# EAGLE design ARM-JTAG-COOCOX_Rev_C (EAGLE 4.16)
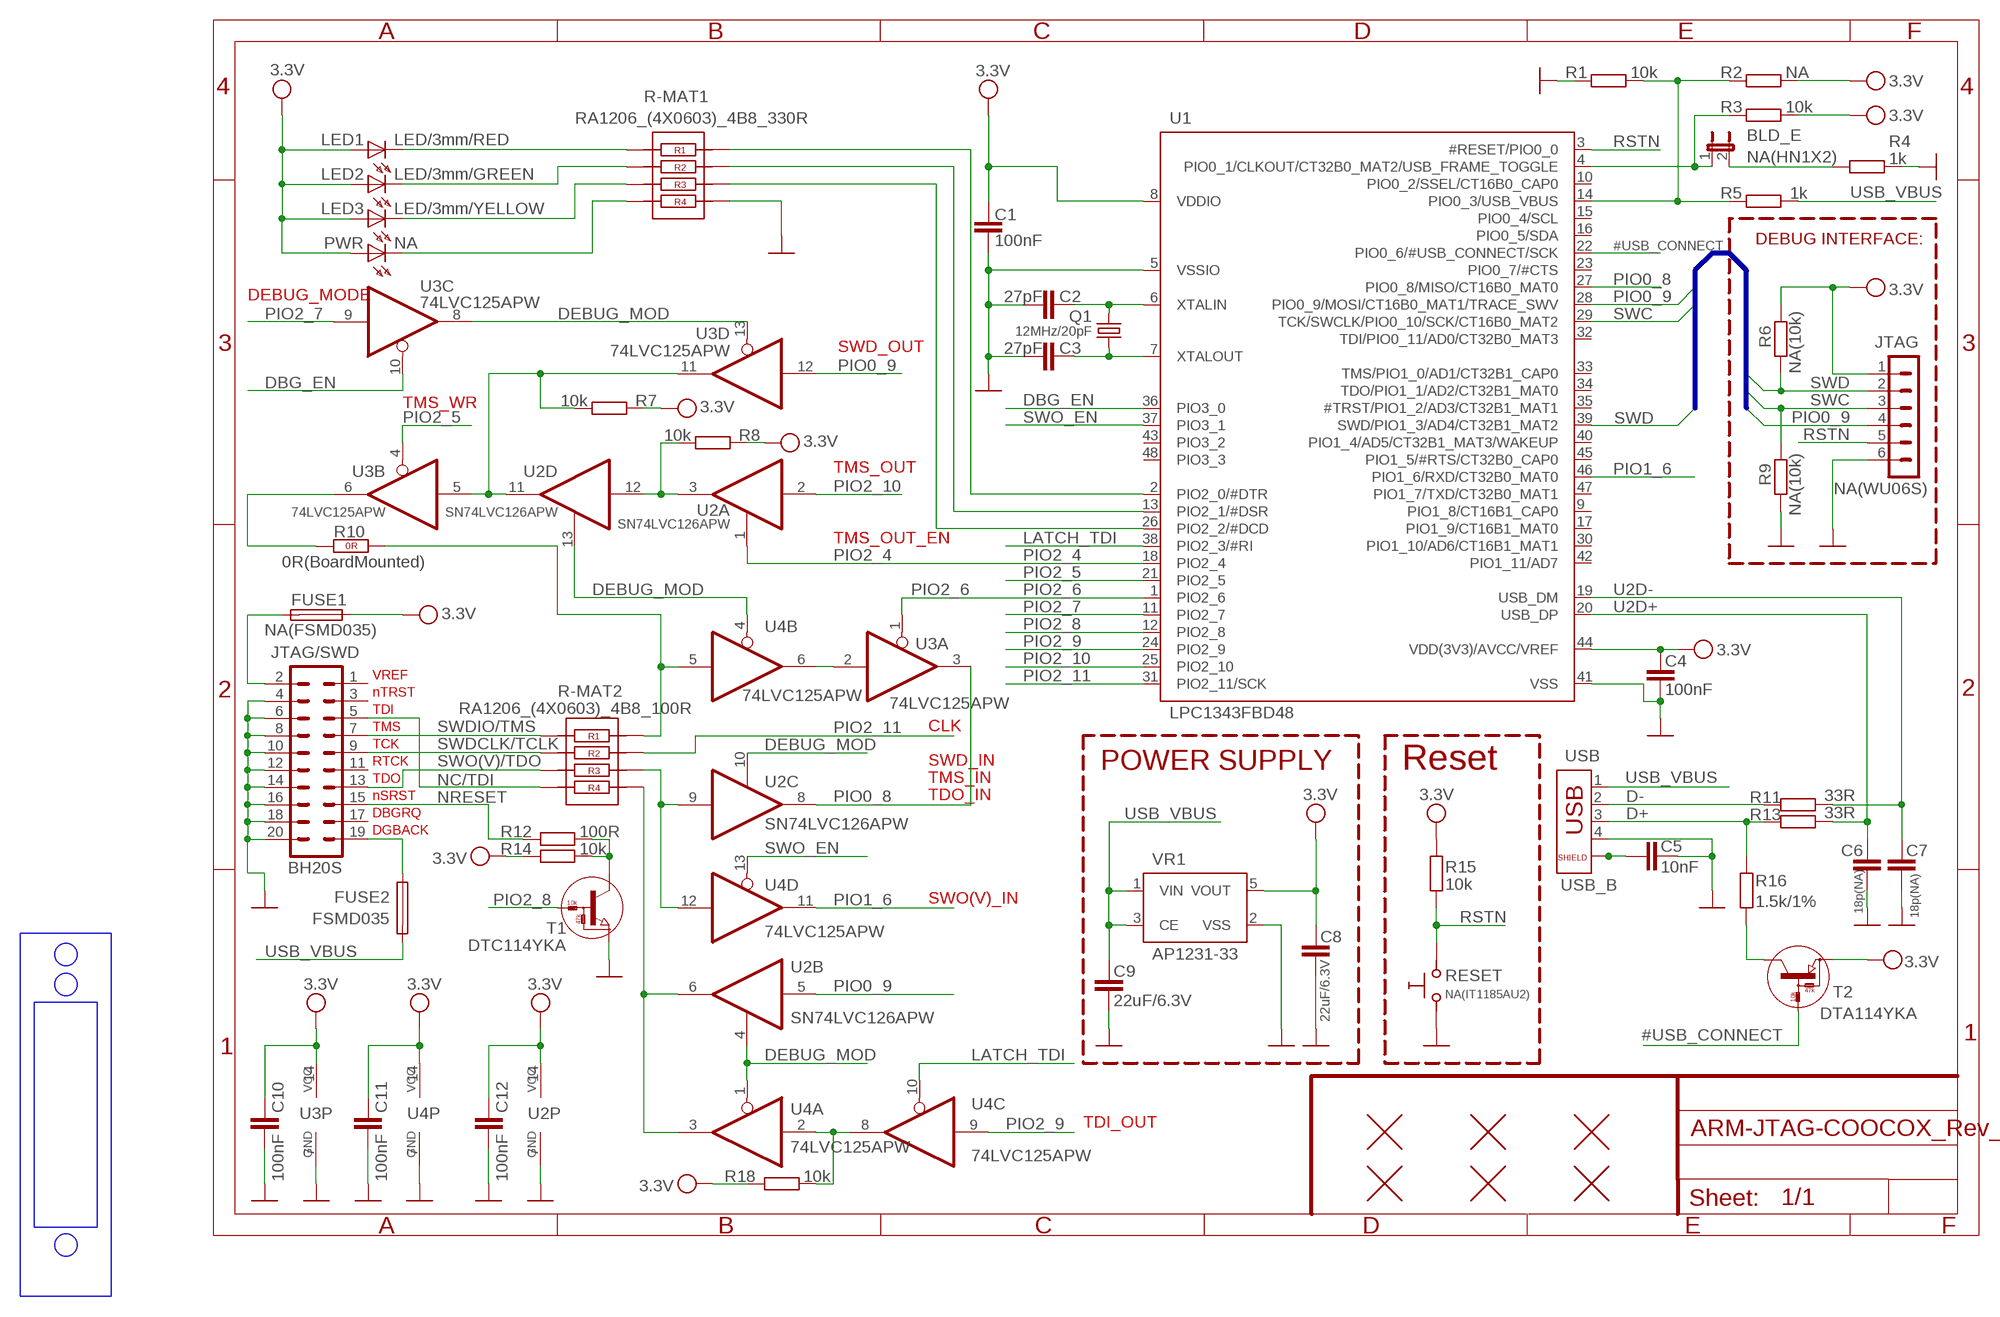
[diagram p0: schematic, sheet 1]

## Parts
BLD_E  NA(HN1X2)  JP1E  [JP1]
C1  100nF  C-EUC0603_DWS  [C0603_DWS]
C2  27pF  C-EUC0603_DWS  [C0603_DWS]
C3  27pF  C-EUC0603_DWS  [C0603_DWS]
C4  100nF  C-EUC0603_DWS  [C0603_DWS]
C5  10nF  C-EUC0603_DWS  [C0603_DWS]
C6  18p(NA)  C-EUC0603_DWS_NA  [C0603_DWS_NA]
C7  18p(NA)  C-EUC0603_DWS_NA  [C0603_DWS_NA]
C8  22uF/6.3V  C-EUC0603_DWS  [C0603_DWS]
C9  22uF/6.3V  C-EUC0603_DWS  [C0603_DWS]
C10  100nF  C-EUC0603_DWS  [C0603_DWS]
C11  100nF  C-EUC0603_DWS  [C0603_DWS]
C12  100nF  C-EUC0603_DWS  [C0603_DWS]
FUSE1  NA(FSMD035)  FUSE  [1206]
FUSE2  FSMD035  FUSE  [1206]
JTAG  NA(WU06S)  CON6WUO6S  [WU06S]
JTAG/SWD  BH20S  ML20CHANGED  [ML20L_PADS_CHANGED]
LED1  LED/3mm/RED  LEDLED_SMD_90  [LED_PADS]
LED2  LED/3mm/GREEN  LEDLED_SMD_90  [LED_PADS]
LED3  LED/3mm/YELLOW  LEDLED_SMD_90  [LED_PADS]
PWR  NA  LEDLED_SMD_90  [LED_PADS]
Q1  12MHz/20pF  HC49/S1  [HC49/SMD2_THIN]
R1  10k  R-EU_R0603_5MIL_DWS  [R0603_5MIL_DWS]
R2  NA  R-EU_R0603_5MIL_DWS  [R0603_5MIL_DWS]
R3  10k  R-EU_R0603_5MIL_DWS  [R0603_5MIL_DWS]
R4  1k  R-EU_R0603_5MIL_DWS  [R0603_5MIL_DWS]
R5  1k  R-EU_R0603_5MIL_DWS  [R0603_5MIL_DWS]
R6  NA(10k)  R-EU_R0603_5MIL_DWS  [R0603_5MIL_DWS]
R7  10k  R-EU_R0603_5MIL_DWS  [R0603_5MIL_DWS]
R8  10k  R-EU_R0603_5MIL_DWS  [R0603_5MIL_DWS]
R9  NA(10k)  R-EU_R0603_5MIL_DWS  [R0603_5MIL_DWS]
R10  0R(BoardMounted)  R_0R0R(NA)  [0603_0R]
R11  33R  R-EU_R0603_5MIL_DWS  [R0603_5MIL_DWS]
R12  100R  R-EU_R0603_5MIL_DWS  [R0603_5MIL_DWS]
R13  33R  R-EU_R0603_5MIL_DWS  [R0603_5MIL_DWS]
R14  10k  R-EU_R0603_5MIL_DWS  [R0603_5MIL_DWS]
R15  10k  R-EU_R0603_5MIL_DWS  [R0603_5MIL_DWS]
R16  1.5k/1%  R-EU_R0603_5MIL_DWS  [R0603_5MIL_DWS]
R18  10k  R-EU_R0603_5MIL_DWS  [R0603_5MIL_DWS]
R-MAT1  RA1206_(4X0603)_4B8_330R  R_MATRIX_4  [R_MATRIX_4]
R-MAT2  RA1206_(4X0603)_4B8_100R  R_MATRIX_4  [R_MATRIX_4]
RESET  NA(IT1185AU2)  SW-TAKTIT1185AU2  [IT1185AU2]
T1  DTC114YKA  DIGITAL_TRANSISTORS-NPNDTC114YKA  [SOT-23]
T2  DTA114YKA  DIGITAL_TRANSISTORS-PNPDTA114YKA  [SOT-23]
U1  LPC1343FBD48  [LQFP48]
U2  SN74LVC126APW  74LVC126A  [TSSOP14]
U3  74LVC125APW  74LVC125A  [TSSOP14]
U4  74LVC125APW  74LVC125A  [TSSOP14]
U$1  FIDUCIAL1X2  [FIDUCIAL-1X2]
U$2  FIDUCIAL1X2  [FIDUCIAL-1X2]
U$3  FIDUCIAL1X2  [FIDUCIAL-1X2]
U$4  FIDUCIAL1X2  [FIDUCIAL-1X2]
U$5  FIDUCIAL1X2  [FIDUCIAL-1X2]
U$6  FIDUCIAL1X2  [FIDUCIAL-1X2]
USB  USB_B  USB_SHIELDUSB_B_SMD  [USB_PADS]
VR1  AP1231-33  [SOT-23-5]

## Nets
#USB_CONNECT: T2.1(B) U1.22(PIO0_6/#USB_CONNECT/SCK)
D+: R13.2 R16.1 USB.3
D-: R11.2 USB.2
DBG_EN: U1.36(PIO3_0) U3.10(C:#OE)
DEBUG_MOD: U2.4(B:OE) U2.10(C:OE) U2.13(D:OE) U3.8(C:O) U3.13(D:#OE) U4.1(A:#OE) U4.4(B:#OE)
GND: C1.2 C2.2 C3.2 C4.2 C5.2 C6.2 C7.2 C8.2 C9.2 C10.2 C11.2 C12.2 JTAG.6 JTAG/SWD.4 JTAG/SWD.6 JTAG/SWD.8 JTAG/SWD.10 JTAG/SWD.12 JTAG/SWD.14 JTAG/SWD.16 JTAG/SWD.18 JTAG/SWD.20 R1.2 R4.2 R9.1 R-MAT1.4.2 RESET.2 T1.2(E) U1.5(VSSIO) U1.41(VSS) U2.7(P:GND) U3.7(P:GND) U4.7(P:GND) USB.4 VR1.2(VSS)
IN_TDO: R-MAT2.3.2 U2.9(C:I) U4.12(D:I)
IN_TMS: R10.2(1.2) R-MAT2.1.2 U4.5(B:I)
ISP_E: BLD_E.1 R3.2 U1.4(PIO0_1/CLKOUT/CT32B0_MAT2/USB_FRAME_TOGGLE)
LATCH_TDI: U1.38(PIO2_3/#RI) U4.10(C:#OE)
N$1: PWR.2-K(C) R-MAT1.4.1
N$2: C2.1 Q1.2 U1.6(XTALIN)
N$3: LED1.2-K(C) R-MAT1.1.1
N$4: LED2.2-K(C) R-MAT1.2.1
N$5: FUSE2.1 JTAG/SWD.19
N$6: R12.1 R14.1 T1.3(C)
N$7: C3.1 Q1.1 U1.7(XTALOUT)
N$8: FUSE1.2 JTAG/SWD.2
N$9: LED3.2-K(C) R-MAT1.3.1
N$10: R18.1 U4.2(A:I) U4.8(C:O)
N$13: U3.2(A:I) U4.6(B:O)
N$14: R8.1 U2.3(A:O) U2.12(D:I)
N$15: BLD_E.2 R4.1
N$16: R7.1 U2.11(D:O) U3.5(B:I) U3.11(D:O)
N$41: R-MAT1.3.2 U1.26(PIO2_2/#DCD)
N$43: R-MAT1.2.2 U1.13(PIO2_1/#DSR)
N$44: R-MAT1.1.2 U1.2(PIO2_0/#DTR)
N$52: R16.2 T2.3(C)
NC/TDI: JTAG/SWD.5 R-MAT2.4.1
NRESET: JTAG/SWD.15 R12.2
OUT_TDI: R-MAT2.4.2 U2.6(B:O) U4.3(A:O)
OUT_TMS: R10.1(1.1) U3.6(B:O)
PIO0_8: U1.27(PIO0_8/MISO/CT16B0_MAT0) U2.8(C:O) U3.3(A:O)
PIO0_9: JTAG.4 U1.28(PIO0_9/MOSI/CT16B0_MAT1/TRACE_SWV) U2.5(B:I) U3.12(D:I)
PIO1_6: U1.46(PIO1_6/RXD/CT32B0_MAT0) U4.11(D:O)
PIO2_4: U1.18(PIO2_4) U2.1(A:OE)
PIO2_5: U1.21(PIO2_5) U3.4(B:#OE)
PIO2_6: U1.1(PIO2_6) U3.1(A:#OE)
PIO2_7: U1.11(PIO2_7) U3.9(C:I)
PIO2_8: T1.1(B) U1.12(PIO2_8)
PIO2_9: U1.24(PIO2_9) U4.9(C:I)
PIO2_10: U1.25(PIO2_10) U2.2(A:I)
PIO2_11: R-MAT2.2.2 U1.31(PIO2_11/SCK)
PIO3: R1.1 R2.2 R5.2 U1.14(PIO0_3/USB_VBUS)
RSTN: JTAG.5 R15.1 RESET.1 U1.3(#RESET/PIO0_0)
SWC: JTAG.3 R9.2 U1.29(TCK/SWCLK/PIO0_10/SCK/CT16B0_MAT2)
SWD: JTAG.2 R6.1 U1.39(SWD/PIO1_3/AD4/CT32B1_MAT2)
SWDCLK/TCLK: JTAG/SWD.9 R-MAT2.2.1
SWDIO/TMS: JTAG/SWD.7 R-MAT2.1.1
SWO(V)/TDO: JTAG/SWD.13 R-MAT2.3.1
SWO_EN: U1.37(PIO3_1) U4.13(D:#OE)
U2D+: C6.1 R13.1 U1.20(USB_DP)
U2D-: C7.1 R11.1 U1.19(USB_DM)
USB_SHIELD: C5.1 USB.P$5 USB.P$6
USB_VBUS: C9.1 FUSE2.2 R5.1 USB.1 VR1.1(VIN) VR1.3(CE)
VCC: C1.1 C4.1 C8.1 C10.1 C11.1 C12.1 FUSE1.1 JTAG.1 LED1.1-A(A) LED2.1-A(A) LED3.1-A(A) PWR.1-A(A) R2.1 R3.1 R6.2 R7.2 R8.2 R14.2 R15.2 R18.2 T2.2(E) U1.8(VDDIO) U1.44(VDD(3V3)/AVCC/VREF) U2.14(P:VCC) U3.14(P:VCC) U4.14(P:VCC) VR1.5(VOUT) ; supply symbol labelled 3.3V
Unconnected: JTAG/SWD.1 JTAG/SWD.3 JTAG/SWD.11 JTAG/SWD.17 U1.9(PIO1_8/CT16B1_CAP0) U1.10(PIO0_2/SSEL/CT16B0_CAP0) U1.15(PIO0_4/SCL) U1.16(PIO0_5/SDA) U1.17(PIO1_9/CT16B1_MAT0) U1.23(PIO0_7/#CTS) U1.30(PIO1_10/AD6/CT16B1_MAT1) U1.32(TDI/PIO0_11/AD0/CT32B0_MAT3) U1.33(TMS/PIO1_0/AD1/CT32B1_CAP0) U1.34(TDO/PIO1_1/AD2/CT32B1_MAT0) U1.35(#TRST/PIO1_2/AD3/CT32B1_MAT1) U1.40(PIO1_4/AD5/CT32B1_MAT3/WAKEUP) U1.42(PIO1_11/AD7) U1.43(PIO3_2) U1.45(PIO1_5/#RTS/CT32B0_CAP0) U1.47(PIO1_7/TXD/CT32B0_MAT1) U1.48(PIO3_3)

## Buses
SWD,SWC,MOSI/SWV

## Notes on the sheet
- DEBUG INTERFACE:
- DEBUG_MODE
- SWD_OUT
- TMS_WR
- TMS_OUT
- TMS_OUT_EN
- VREF
- nTRST
- TDI
- TMS | CLK
- TCK
- RTCK | SWD_IN
- POWER SUPPLY | Reset
- TDO | TMS_IN
- nSRST | TDO_IN
- DBGRQ
- DGBACK
- SWO(V)_IN
- TDI_OUT

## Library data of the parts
BLD_E = jumper:JP1E: JUMPER
C1-C12 = rcl:C-EU: CAPACITOR, European symbol
FUSE1 FUSE2 = gogo:FUSE
JTAG = Penko:CON6: CONNECTORS - 6 PINS
JTAG/SWD = con-harting-ml:ML20: HARTING
LED1-LED3 PWR = DOUBLE-SIDE:LED
Q1 = crystal:HC49/S: CRYSTAL
R1-R9 R11-R16 R18 = rcl:R-EU_: RESISTOR, European symbol
R10 = OLIMEX_DISCRET:R_0R
R-MAT1 R-MAT2 = OLIMEX_DISCRET:R_MATRIX_4
RESET = gogo:SW-TAKT
T1 = OLIMEX_DISCRET:DIGITAL_TRANSISTORS-NPN: DTC114YKA Digital Transistor - NPN
T2 = OLIMEX_DISCRET:DIGITAL_TRANSISTORS-PNP: DTA114YKA Digital Transistor - PNP
U1 = OLIMEX_IC:LPC1343: LPC1343FBD48 32-bit ARM Cortex-M3 microcontroller; up to 32 kB flash and 8 kB SRAM; USB Device
U2 = OLIMEX_IC:74*126: Quad bus BUFFER, 3-state
U3 U4 = OLIMEX_IC:74*125: Quad bus BUFFER, 3-state
U$1-U$6 = SparkFunEagle-6-6-07:FIDUCIAL: Fiducial Alignment Points
USB = OLIMEX_CONNECTORS:USB_SHIELD
VR1 = OLIMEX_DISCRET:AP1231

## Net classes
1 pwr: width 0.35 mm, drill 0.25 mm

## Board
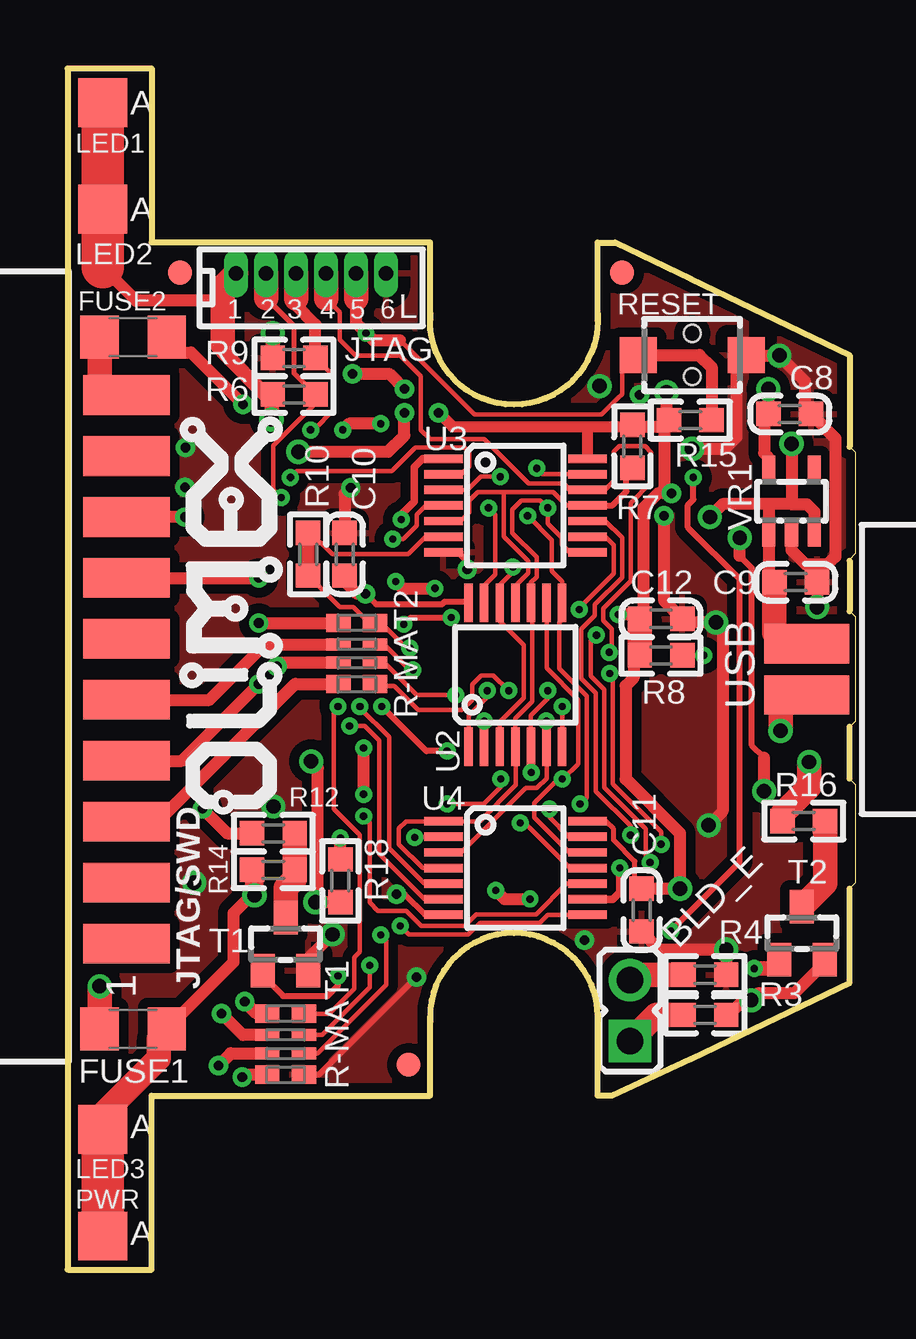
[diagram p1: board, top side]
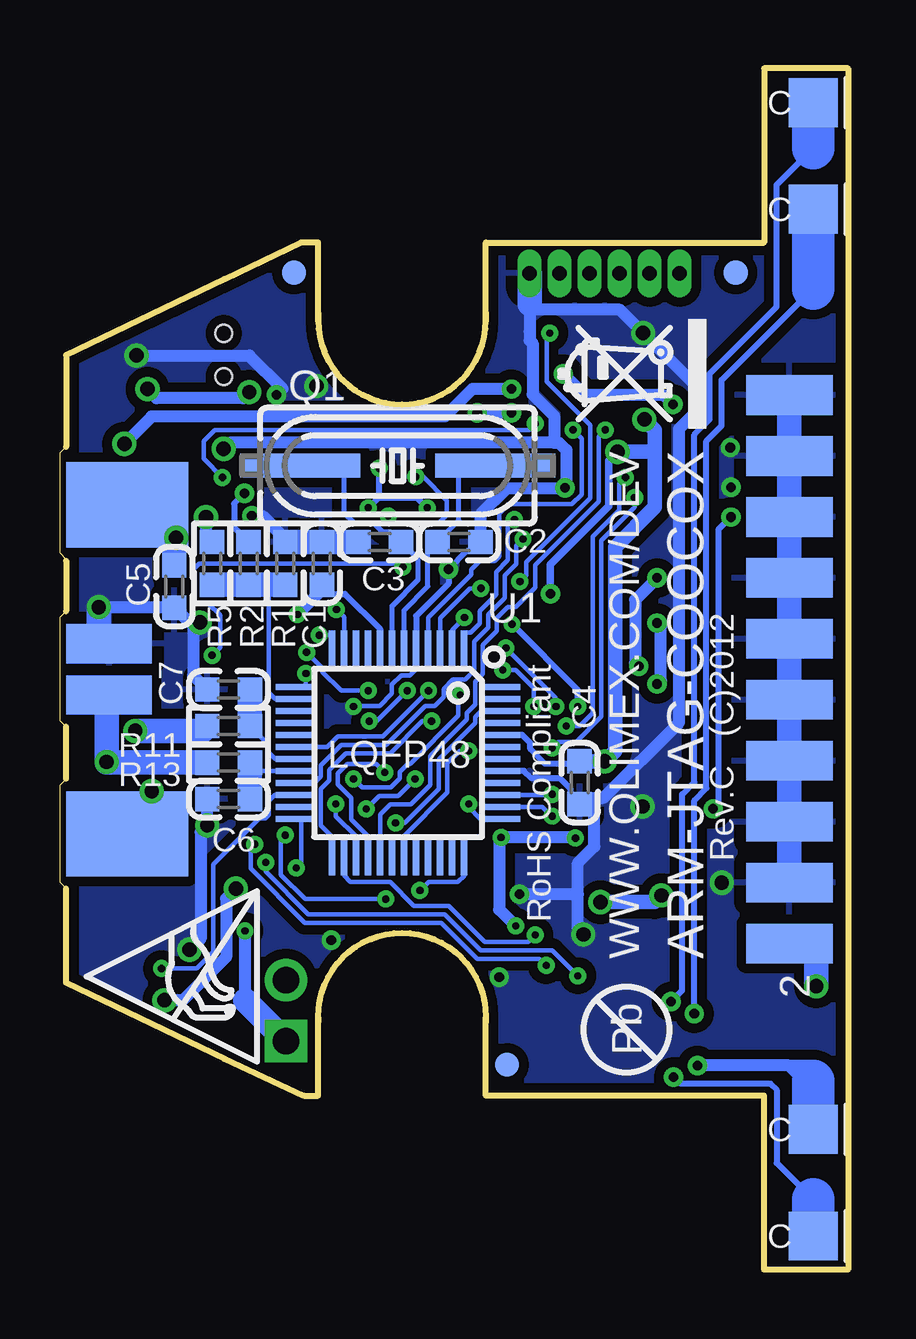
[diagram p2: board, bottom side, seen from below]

Size 32.84 x 50.07 mm. Coordinates in mm from the lower left corner, seen from the top.
Outline: 15.1,10.54 15.1,7.25 3.5,7.25 3.5,0 0,0 0,50.07 3.5,50.07 3.5,42.81 15.1,42.81 15.1,39.55
Outline: 15.1,10.54 15.1,10.3
Outline: 15.1,39.89 15.1,39.55
Outline: 22.08,10.54 22.08,7.25 22.68,7.25 25.98,8.78 32.58,11.95 32.58,15.89 32.84,16.14 32.84,20.21 32.58,20.46 32.58,22.62 32.84,22.88 32.84,27.19 32.58,27.45 32.58,29.56
Outline: 22.08,10.54 22.08,10.3
Outline: 22.08,39.89 22.08,39.55
Outline: 22.08,39.55 22.08,42.81 22.8,42.81 25.98,41.29 32.58,38.12 32.58,34.31 32.84,34.05 32.84,29.86 32.58,29.61
Outline: 22.08,39.55 arc-180 15.1,39.55
Outline: 22.08,10.54 arc180 15.1,10.54
Copper layers (1+16): Top 0.035mm / dielectric 1.5mm / Bottom 0.035mm
Design rules "default": minimum track width 6.5mil, minimum drill 11.5mil, track to track 7mil, track to pad 7mil, pad to pad 7mil, via to via 7mil, smd to smd 1mil, copper to edge 8mil, drill to drill 10mil, minimum pad ring 8mil, minimum via ring 8mil, stop-mask expansion 4mil, vias tented up to drill 25mil, thermal gap 20mil
Milling: area -19.8,4.2 to -16.6,7.4; area -19.8,42.6 to -16.6,45.8; area -19.8,47 to -16.6,50.2; 8 lines

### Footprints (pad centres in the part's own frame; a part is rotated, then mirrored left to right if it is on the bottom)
JP1 = drill 1.1 pad 1.778 square: 1 0,-1.27 | drill 1.1 pad 1.778 round: 2 0,1.27
C0603_DWS = smd 1.016 x 1.016: 1 -0.889,0; 2 0.889,0
C0603_DWS_NA = smd 1.016 x 1.016: 1 -0.889,0; 2 0.889,0
1206 = smd 1.6 x 1.8: 1 -1.4,0; 2 1.4,0
WU06S = drill 0.6 pad 0.991 long: 1 -3.125,0; 2 -1.875,0; 3 -0.625,0; 4 0.625,0; 5 1.875,0; 6 3.125,0
ML20L_PADS_CHANGED = smd 1.651 x 3.607: 1 -11.43,-3.404; 3 -8.89,-3.404; 5 -6.35,-3.404; 7 -3.81,-3.404; 9 -1.27,-3.404; 11 1.27,-3.404; 13 3.81,-3.404; 15 6.35,-3.404; 17 8.89,-3.404; 19 11.43,-3.404 | smd 1.651 x 3.607 bottom: 2 -11.43,-3.404; 4 -8.89,-3.404; 6 -6.35,-3.404; 8 -3.81,-3.404; 10 -1.27,-3.404; 12 1.27,-3.404; 14 3.81,-3.404; 16 6.35,-3.404; 18 8.89,-3.404; 20 11.43,-3.404
LED_PADS = smd 2.032 x 2.032: 1-A 0,0 | smd 2.032 x 2.032 bottom: 2-K 0,0
HC49/SMD2_THIN = smd 5 x 1: 1 -4.064,0; 2 4.064,0
R0603_5MIL_DWS = smd 1.016 x 1.016: 1 -0.889,0; 2 0.889,0
0603_0R = smd 1.016 x 1.016: 1 -0.889,0; 2 0.889,0
R_MATRIX_4 = smd 1.016 x 0.762: 1.1 -0.762,1.27; 1.2 0.762,1.27; 4.1 -0.762,-1.27; 4.2 0.762,-1.27 | smd 1.016 x 0.508: 2.1 -0.762,0.381; 2.2 0.762,0.381; 3.1 -0.762,-0.381; 3.2 0.762,-0.381
IT1185AU2 = smd 1.55 x 1.5: 1 -2.25,0; 2 2.25,0 | hole 0.7: 0,-0.9; 0,0.9
SOT-23 = smd 1 x 1.4: 1 -0.95,-1.1; 2 0.95,-1.1; 3 0,1.1
LQFP48 = smd 0.254 x 1.6: 1 -2.75,-4.3; 2 -2.25,-4.3; 3 -1.75,-4.3; 4 -1.25,-4.3; 5 -0.75,-4.3; 6 -0.25,-4.3; 7 0.25,-4.3; 8 0.75,-4.3; 9 1.25,-4.3; 10 1.75,-4.3; 11 2.25,-4.3; 12 2.75,-4.3; 25 2.75,4.3; 26 2.25,4.3; 27 1.75,4.3; 28 1.25,4.3; 29 0.75,4.3; 30 0.25,4.3; 31 -0.25,4.3; 32 -0.75,4.3; 33 -1.25,4.3; 34 -1.75,4.3; 35 -2.25,4.3; 36 -2.75,4.3 | smd 1.6 x 0.254: 13 4.3,-2.75; 14 4.3,-2.25; 15 4.3,-1.75; 16 4.3,-1.25; 17 4.3,-0.75; 18 4.3,-0.25; 19 4.3,0.25; 20 4.3,0.75; 21 4.3,1.25; 22 4.3,1.75; 23 4.3,2.25; 24 4.3,2.75; 37 -4.3,2.75; 38 -4.3,2.25; 39 -4.3,1.75; 40 -4.3,1.25; 41 -4.3,0.75; 42 -4.3,0.25; 43 -4.3,-0.25; 44 -4.3,-0.75; 45 -4.3,-1.25; 46 -4.3,-1.75; 47 -4.3,-2.25; 48 -4.3,-2.75
TSSOP14 = smd 0.35 x 1.6: 1 -1.95,-3; 2 -1.3,-3; 3 -0.65,-3; 4 0,-3; 5 0.65,-3; 6 1.3,-3; 7 1.95,-3; 8 1.95,3; 9 1.3,3; 10 0.65,3; 11 0,3; 12 -0.65,3; 13 -1.3,3; 14 -1.95,3
FIDUCIAL-1X2 = smd 1 x 1: 1 0,0
USB_PADS = smd 1.626 x 3.556: 1 1.067,10.287; 2 -1.067,10.287 | smd 1.626 x 3.556 bottom: 3 -1.067,10.287; 4 1.067,10.287 | smd 3.556 x 5.08 bottom: P$5 -6.858,11.049; P$6 6.858,11.049
SOT-23-5 = smd 0.55 x 1.2: 1 -0.95,-1.3; 2 0,-1.3; 3 0.95,-1.3; 4 0.95,1.3; 5 -0.95,1.3

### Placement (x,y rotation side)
BLD_E  23.43,10.8 0 top
C1  21.93,29.44 90 bottom
C2  16.21,30.33 0 bottom
C3  19.51,30.33 180 bottom
C4  11.18,20.3 270 bottom
C5  28.07,28.48 270 bottom
C6  25.81,19.61 180 bottom
C7  25.81,24.18 180 bottom
C8  30.08,35.66 0 top
C9  30.34,28.65 0 top
C10  11.54,29.82 90 top
C11  23.91,14.99 270 top
C12  24.72,27.13 0 top
FUSE1  2.73,10.04 180 top
FUSE2  2.73,38.86 0 top
JTAG  10.14,41.53 0 top
JTAG/SWD  -0.96,25.02 90 top
LED1  1.46,48.64 180 top
LED2  1.46,44.2 180 top
LED3  1.46,5.84 180 top
PWR  1.46,1.4 180 top
Q1  18.77,33.51 0 bottom
R1  23.45,29.44 90 bottom
R2  24.98,29.44 270 bottom
R3  26.55,10.62 180 top
R4  26.55,12.3 0 top
R5  26.5,29.44 270 bottom
R6  9.43,36.48 180 top
R7  23.53,34.32 90 top
R8  24.72,25.61 180 top
R9  9.43,38 0 top
R10  10.02,29.82 270 top
R11  25.81,22.66 180 bottom
R12  8.57,18.19 180 top
R13  25.81,21.14 180 bottom
R14  8.57,16.66 180 top
R15  25.94,35.41 180 top
R16  30.67,18.7 0 top
R18  11.36,16.21 270 top
R-MAT1  9.08,9.4 0 top
R-MAT2  12.05,25.68 0 top
RESET  26.02,38.13 0 top
T1  9.08,13.57 0 top
T2  30.59,14.02 0 top
U1  18.75,21.54 180 bottom
U2  18.65,24.79 0 top
U3  18.65,31.85 270 top
U4  18.65,16.74 270 top
U$1  14.21,8.54 180 top
U$2  23.1,41.56 0 top
U$3  4.68,41.56 0 top
U$4  4.68,41.56 0 bottom
U$5  14.21,8.54 0 bottom
U$6  23.1,41.56 0 bottom
U$7  [OLIMEX1_V]  9.08,36.71 90 top
U$9  [PB_SMALL]  9.23,10.01 90 bottom
U$10  [RECYCLE_BIN1/8]  5.9,35.05 90 bottom
U$14  [ESD_SYMBOL]  24.62,8.66 90 bottom
USB  41.08,25.02 90 top
VR1  30.16,32.03 0 top

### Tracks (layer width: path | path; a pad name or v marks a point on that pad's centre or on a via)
#USB_CONNECT  (via drill 0.3)
  Top 0.61: T2.1 29.27,12.55 v28.61,12.55
  Bottom 0.178: U1.22 23.88,19.79 24.14,19.54 24.14,18.95 24.29,18.8 24.54,18.8 26.45,16.89 26.45,13.24 27.13,12.55 v28.61,12.55
D+  (via drill 0.6)
  Top 1.016: v30.89,21.16 30.89,20.12 29.78,19 R16.1
  Bottom 1.016: USB.3 30.89,23.95 30.89,21.14 | 30.89,21.14 v30.89,21.16 | R13.2 30.89,21.14
D-  (via drill 0.6)
  Top 1.016: USB.2 29.7,23.95 v29.7,22.46
  Bottom 1.016: R11.2 26.91,22.46 v29.7,22.46
DBG_EN  (via drill 0.3)
  Top 0.178: U3.10 22.4,31.2 23.1,30.51 23.1,28.86 21.95,27.71 21.95,27.26 21.39,26.7 21.39,24.64 22,24.03 22,19.94 23.45,18.49 v23.45,18.11
  Top 0.508: v17.84,15.8 18.19,15.45 v19.26,15.45
  Bottom 0.178: v19.26,15.45 22.61,15.45 23.63,16.46 23.63,17.93 v23.45,18.11 | U1.36 16,16.42 16.26,16.16 17.48,16.16 v17.84,15.8
DEBUG_MOD  (via drill 0.3)
  Top 0.178: U4.4 14.79,16.74 13.8,17.73 13.8,18.39 14.1,18.69 U4.1 17.17,18.69 18.68,20.2 18.68,21.08 18.65,21.11 U2.4 18.65,22.96 19.36,23.68 19.36,27.29 19.3,27.35 U2.10 19.3,28.64 19.54,28.88 19.54,29.7 18.52,30.71 18.52,31.68 18.91,32.06 19.69,32.06 v20,31.75 20,31.09 20.58,30.51 20.58,30.23 20.91,29.9 U3.8 | U2.13 17.35,28.52 17.81,28.98 17.81,31.47 v17.53,31.75 | U3.13 19.79,33.15 v19.54,33.4
  Bottom 0.254: v20,31.75 19.57,32.18 19.54,32.18 | 19.54,32.18 17.97,32.18 v17.53,31.75 | 19.54,32.18 v19.54,33.4
GND  (via drill 0.3, 0.4, 0.6)
  Top 0.178: U2.7 v20.6,23.47 v20.61,23.47
  Top 0.203: T1.2 10.03,12.97
  Top 0.254: U4.7 14.89,14.79 14.03,15.65 v13.7,15.65 | U3.7 16.26,29.9 16.64,29.52 v16.64,29.19 | R-MAT1.4.2 10.47,8.13 v14.54,12.19
  Top 0.508: 31.22,29.39 30.74,29.39 30.16,29.97 VR1.2 | v31.22,27.61 C9.2 31.22,29.39 | 31.22,29.39 31.66,29.39 31.99,29.72 31.99,34.65 C8.2 30.72,35.66 30.72,37.04 v29.65,38.1 28.29,38.1 RESET.2 27.87,37.73 27.87,34.7 27.39,34.22 v26.02,34.22 | v27.44,13.34 R4.2 | 10.03,12.97 v11.03,13.97 | v27.44,13.34 24.67,13.34 C11.2 | v27.44,13.34 27.47,13.34 | v26.7,18.52 27.29,19.1 27.29,26.7 v27.01,26.98 25.76,26.98 C12.2 24.85,27.89 v24.85,31.42 | C10.2 11.54,32.34 v11.79,32.59
  Top 0.61: v8.54,39.04 R9.1
  Bottom 0.178: U1.5 18,25.03 18.27,24.77 18.63,24.77 19.01,24.39 19.01,24.01 19.51,23.5 20.58,23.5 v20.61,23.47
  Bottom 0.254: C4.2 11.56,19.41 11.56,20.04 12,20.47 13.19,20.47 13.51,20.79 U1.41 | U1.5 18,27.24 16.64,28.6 v16.64,29.19 15.88,29.95 15.7,29.95 C2.2
  Bottom 0.508: v27.44,13.34 26.98,13.79 26.98,18.24 v26.7,18.52 | v26.7,18.52 C6.2 v26.7,18.52 | 13.27,40.01 9.51,40.01 v8.54,39.04 6.41,36.91 6.41,35.69 7.04,35.05 7.04,22.81 10.19,19.66 10.93,19.66 C4.2 10.57,19.41 10.57,17.63 11.26,16.94 11.26,15.65 | 13.27,40.01 13.27,40.24 | 13.27,40.01 13.27,39.12 13.27,38.74 13.14,38.61 13.14,36.48 12.25,35.59 12.25,34.47 | v26.02,34.22 25.76,34.47 12.25,34.47 | v11.03,13.97 11.26,14.2 11.26,15.65 | 11.26,15.65 v13.7,15.65 | C2.2 15.32,31.47 14.23,32.57 12.02,32.57 11.89,32.69 | 11.89,32.69 11.74,32.84 11.74,34.17 12.05,34.47 12.25,34.47 | 11.89,32.69 v11.79,32.59 | R1.2 23.45,30.46 24.42,31.42 v24.85,31.42 | 27.29,26.98 27.29,24.77 C7.2 | 28.05,27.59 27.44,26.98 27.29,26.98 | 27.29,26.98 v27.01,26.98 | 28.05,27.59 C5.2 | v31.22,27.61 28.07,27.61 28.05,27.59 | v23.82,36.46 23.57,36.72 24.95,38.1 v29.65,38.1
  Bottom 1.016: USB.4 31.22,26.09 v31.22,27.61 | 13.27,40.24 JTAG.6 | C3.2 C1.2 R1.2 | JTAG/SWD.4 JTAG/SWD.6 JTAG/SWD.8 JTAG/SWD.10 JTAG/SWD.12 JTAG/SWD.14 JTAG/SWD.16 JTAG/SWD.18 JTAG/SWD.20
  other vias: 21.53,13.73 4.88,32.62 22.16,36.83 4.91,34.27 5.27,16.13 8.57,19.31
  pour Top (isolate 0.406, rank 6): -1.59,50.42 35.24,50.42 35.24,-0.38 -1.59,-0.38
  pour Bottom (isolate 0.406, rank 5): -4.13,52.96 37.78,52.96 37.78,-2.92 -4.13,-2.92
IN_TDO  (via drill 0.3)
  Top 0.178: U2.9 19.95,25.07 21.27,23.75 21.27,21.08 20.63,20.45 v20.61,20.45 20.43,20.45 19.44,19.46 19.44,18.85 20.9,17.39 U4.12 | R-MAT2.3.2 13.19,25.3 14.54,23.95 v16.16,23.95
  Bottom 0.178: v20.61,20.45 20.25,20.09 19.06,20.09 18.68,20.47 18.68,20.75 18.35,21.08 18.24,21.08 16.24,23.09 16.24,23.88 v16.16,23.95
IN_TMS  (via drill 0.3)
  Top 0.178: R10.2 11.34,27.61 11.89,27.61 12.56,26.95 R-MAT2.1.2 13.06,26.95 14.1,25.91 v14.26,25.91 | U4.5 14.86,16.09 13.39,17.55 13.39,22.2 12.17,23.42 v12.17,23.47
  Bottom 0.178: v12.17,23.47 12.17,23.83 v14.26,25.91
ISP_E  (via drill 0.3)
  Top 0.254: v25.13,14.12 28,17 28,28.78 25.84,30.94 25.84,31.88 26.07,32.11 v26.07,33.02
  Top 0.508: v13.04,35.26 11.72,35.26 v11.46,35
  Top 1.016: BLD_E.1 24.52,10.62 R3.2
  Bottom 0.178: U1.4 17.5,27.18 15.7,28.97 15.7,29.19 15.35,29.54 14.71,29.54 14.54,29.72 14.54,31.52 14.16,31.9 11.51,31.9 11.11,32.31 11.11,34.65 v11.46,35 | v26.07,33.02 26.86,33.81 26.86,34.55 26.4,35 13.29,35 v13.04,35.26
  Bottom 0.508: 25.13,11.23 v25.13,14.12
  Bottom 1.016: BLD_E.1 25.13,11.23
LATCH_TDI  (via drill 0.3)
  Top 0.178: U4.10 20.8,16.09 19.51,14.81 17.03,14.81 16.54,14.33 14.74,14.33 14.1,14.96 12.92,14.96 12.58,15.31 12.58,18.65 v12.33,18.9
  Bottom 0.178: U1.38 12.74,19.29 12.35,18.9
  Bottom 0.203: v12.33,18.9 12.35,18.9
N$1  (via drill 0.4)
  Top 0.203: v7.27,8.03 7.37,8.13
  Top 0.508: 7.37,8.13 R-MAT1.4.1
  Bottom 0.254: 1.46,2.92 2.98,4.45 2.98,7.5 3.23,7.75 6.99,7.75 v7.27,8.03
  Bottom 1.778: 1.46,2.92 PWR.2-K
N$2
  Bottom 0.203: U1.6 18.5,27.48 17.51,28.48 17.51,29.92 C2.1 16.21,31.22 16.21,33.51 Q1.2
N$3  (via drill 0.4)
  Top 0.508: R-MAT1.1.1 7.88,10.67 v7.37,11.18
  Bottom 0.254: v7.37,11.18 6.92,11.64 6.92,19.81 6.41,20.32 6.41,34.8 5.77,35.44 5.77,37.34 2.98,40.13 2.98,45.21 1.46,46.74
  Bottom 1.778: 1.46,46.74 LED1.2-K
N$4  (via drill 0.4)
  Top 0.508: R-MAT1.2.1 7.3,9.78 v6.41,10.67
  Bottom 0.254: v6.41,10.67 6.41,19.56 5.9,20.07 5.9,34.55 5.27,35.18 5.27,37.09 1.46,40.9
  Bottom 1.778: 1.46,40.9 LED2.2-K
N$5
  Top 0.508: FUSE2.1 | JTAG/SWD.19 1.33,36.45
  Top 1.016: 1.33,36.45 FUSE2.1
N$6
  Top 0.178: 9.46,16.28 R14.1
  Top 1.016: R14.1 R12.1 | T1.3 9.08,15.9 9.46,16.28
N$7
  Bottom 0.203: Q1.1 21.33,33.51 20.99,33.17 20.99,31.52 20.58,31.12 19.77,31.12 19.39,30.74 19.03,30.74 C3.1 17.91,29.62 17.91,28.76 19,27.67 U1.7
N$8  (via drill 0.6)
  Top 0.508: FUSE1.2
  Top 1.016: FUSE1.2 v1.33,11.81
  Bottom 1.016: JTAG/SWD.2 1.33,13.59 v1.33,11.81
N$9  (via drill 0.4)
  Top 0.508: R-MAT1.3.1 6.79,9.02 v6.28,8.51
  Bottom 0.508: 1.46,7.88 1.46,8.51 2.47,8.51 | 2.47,8.51 v6.28,8.51 | 1.46,7.5 2.47,8.51
  Bottom 1.778: LED3.2-K 1.46,7.5 1.46,7.88
N$10  (via drill 0.3)
  Top 0.178: v13.85,14.33 14.21,13.97 16.7,13.97 17.18,14.46 19.67,14.46 20,14.79 U4.8 | 14.49,18.04 U4.2
  Top 0.203: v14.46,18.01 14.49,18.04
  Top 0.508: R18.1 v11.36,17.99
  Bottom 0.178: v11.36,17.99 11.39,18.01
  Bottom 0.203: v14.46,18.01 14.54,17.93
  Bottom 0.508: 14.54,17.93 14.54,15.01 v13.85,14.33 | 11.39,18.01 v14.46,18.01
N$13  (via drill 0.3)
  Top 0.178: U3.2 16.4,33.15 16.72,33.48 16.72,34.09 16.54,34.27 14.49,34.27 13.5,33.28 9.53,33.28 v9.28,33.02 | U4.6 14.87,15.44 12.99,17.33 12.99,22.05 12.38,22.66 v11.74,22.66
  Bottom 0.178: v11.74,22.66 11.18,22.66 10.64,23.21 10.64,30.56 9.53,31.66 9.53,32.77 v9.28,33.02
N$14  (via drill 0.3)
  Top 0.178: U2.3 18,22.82 19.01,23.83 19.01,26.04 18,27.04 U2.12 18,28.54 18.55,29.09 v18.55,29.29 | v26.5,25.61 R8.1
  Bottom 0.178: v18.55,29.29 18.7,29.44 27.03,29.44 27.29,29.19 27.29,27.94 27.11,27.76 26.65,27.76 26.17,27.28 26.17,25.94 v26.5,25.61
N$15
  Top 1.016: R4.1 23.66,12.3 BLD_E.2
N$16
  Top 0.178: 18.17,32.41 20.23,32.41 20.78,31.85 U3.11 | 18.17,32.41 18.17,30.56 19.18,29.54 19.18,29.03 18.65,28.5 U2.11 | U3.5 15.72,31.27 16.44,31.27 16.72,31.55 16.72,32.06 17.08,32.41 18.17,32.41
  Top 0.254: U3.11 22.69,31.85 23.27,32.44 23.27,33.17 R7.1
N$41  (via drill 0.3)
  Top 0.178: v13.04,13.95 13.27,13.72 13.27,11.86 10.42,9.02 R-MAT1.3.2
  Bottom 0.178: v13.04,13.95 13.32,13.67 15.15,13.67 16.64,15.17 18.09,15.17 19.08,16.16 20.73,16.16 21,16.43 U1.26
N$43  (via drill 0.3)
  Top 0.178: v12.58,12.68 12.58,11.76 10.6,9.78 R-MAT1.2.2 | v22.59,24.84 22.72,24.72 22.72,20.25 24.72,18.24 v24.72,17.73
  Bottom 0.178: v12.58,12.68 12.86,12.96 15.45,12.96 16.95,14.46 22.64,14.46 24.9,16.72 24.9,17.55 v24.72,17.73 | U1.13 22.59,24.29 v22.59,24.84
N$44  (via drill 0.3)
  Top 0.178: v11.26,23.47 11.08,23.29 11.08,19.2 12.17,18.11 12.17,13.24 11.95,13.01 11.95,11.71 10.9,10.67 R-MAT1.1.2
  Top 0.254: v14,26.9 14.28,27.18 v15.98,27.18
  Bottom 0.178: U1.2 16.5,26.66 v15.98,27.18
  Bottom 0.254: v11.26,23.47 11.26,24.16 v14,26.9
N$52
  Top 1.016: T2.3 31.55,16.09 R16.2
NC/TDI
  Top 0.508: R-MAT2.4.1 9.48,24.41 3.74,18.67 JTAG/SWD.5
NRESET  (via drill 0.4)
  Top 0.508: v4.88,31.37 JTAG/SWD.15 | v5.62,19.2 6.64,18.19 R12.2
  Bottom 0.254: v4.88,31.37 5.39,30.86 5.39,19.43 v5.62,19.2
OUT_TDI  (via drill 0.3)
  Top 0.178: U4.3 16.41,17.39 19.08,20.07 19.54,20.07 19.95,20.48 U2.6 | R-MAT2.4.2 12.89,24.34 13.6,24.34 14.61,23.32 16.42,23.32 16.85,23.75 16.85,24.39 17.23,24.77 17.74,24.77 v18.37,24.13
  Top 0.254: U2.6 v19.95,22.86
  Bottom 0.178: v19.95,22.86 19.64,22.86 v18.37,24.13
OUT_TMS
  Top 0.178: U3.6 14.91,30.55 14.18,29.82 11.03,29.82 10.55,30.3 10.42,30.3 R10.1
PIO0_8  (via drill 0.3)
  Top 0.178: v19.16,31.42 20.18,30.41 20.18,29.11 20.6,28.68 U2.8 20.6,27.1 20.48,26.98 20.48,25.05 21.62,23.9 21.62,19.69 v21.34,19.41 | U3.3 16.66,32.5 17.2,33.05 v18.02,33.05
  Bottom 0.178: U1.27 20.5,18.06 21.34,18.9 v21.34,19.41 | v18.02,33.05 17.71,33.05 16.72,32.06 16.72,31.45 17.05,31.12 18.85,31.12 v19.16,31.42
PIO0_9  (via drill 0.3)
  Top 0.178: 10.77,40.47 11.34,39.91 11.34,38.76 12,38.1 13.85,38.1 14.71,37.24 14.71,35 15.1,34.62 17.36,34.62 19.21,32.77 20.66,32.77 20.92,32.5 U3.12 22.37,32.5 22.74,32.87 22.74,34.09 22.97,34.32 24.06,34.32 24.32,34.06 24.32,32.82 23.45,31.96 23.45,28.7 22.31,27.56 22.31,27.05 22.66,26.7 22.66,25.83 v22.56,25.73 | U2.5 19.3,23.1 20,23.8 v20,24.13 | v19.31,20.73 v19.3,20.74
  Top 0.305: v19.3,20.74 U2.5
  Top 1.016: 10.77,40.47 JTAG.4
  Bottom 0.178: v20,24.13 21.12,24.13 21.9,24.92 21.9,25.07 v22.56,25.73 | U1.28 20,18.07 20.71,18.77 20.71,19.66 21.27,20.22 21.27,20.68 20.86,21.08 19.67,21.08 v19.31,20.73
PIO1_6  (via drill 0.3)
  Top 0.178: U4.11 20.91,16.74 19.03,18.62 v18.85,18.62
  Bottom 0.178: v18.85,18.62 18.47,18.62 17.05,20.04 17.05,21.26 15.53,22.79 15.53,23.04 15.28,23.29 U1.46
PIO2_4  (via drill 0.3)
  Top 0.178: U2.1 16.7,23.1 17.48,23.88 v17.48,24.13
  Bottom 0.178: v17.48,24.13 19.39,22.23 21.27,22.23 21.7,21.79 U1.18
PIO2_5  (via drill 0.3)
  Top 0.178: U3.4 14.92,31.85 14.54,31.47 14.54,31.02 13.98,30.46 v13.55,30.46
  Bottom 0.165: 15.63,24.92 15.76,24.79
  Bottom 0.178: U1.21 22.24,20.29 21.98,20.55 21.98,21.01 21.12,21.87 19.24,21.87 17.61,23.5 17.23,23.5 16.85,23.88 16.85,24.21 16.47,24.59 15.96,24.59 15.76,24.79 | 15.63,24.92 15.58,24.97 15.58,26.19 14.99,26.77 14.99,27.31 14.31,27.99 14.31,28.93 13.83,29.42 13.83,30.18 v13.55,30.46
PIO2_6  (via drill 0.3)
  Top 0.305: U3.1 14.78,33.8 14.43,33.45 14.43,32.01 13.9,31.47 v13.9,31.27
  Bottom 0.178: v13.9,31.27 14.18,30.99 14.18,29.57 14.66,29.09 14.66,28.15 15.35,27.46 15.35,26.93 15.72,26.55 16,26.55 U1.1
PIO2_7  (via drill 0.3)
  Top 0.178: U3.9 22.39,30.55 22.74,30.2 22.74,29.01 21.32,27.59 v21.32,27.51
  Bottom 0.178: U1.11 21,27.2 v21.32,27.51
PIO2_8  (via drill 0.3)
  Top 0.178: v22.03,26.44 21.8,26.22 21.8,24.74 22.36,24.18 22.36,20.09 24.09,18.37 24.09,17.15 v24.26,16.97
  Top 0.254: T1.1 8.13,12.26 8.97,11.41 10.83,11.41 11.26,11.84 v11.26,12.25
  Bottom 0.178: v11.26,12.25 12.33,13.31 15.3,13.31 16.8,14.81 22.49,14.81 24.26,16.59 v24.26,16.97 | U1.12 21.5,26.44 v22.03,26.44
PIO2_9  (via drill 0.3)
  Top 0.305: U4.9 22.71,15.44 22.99,15.73 v22.99,16.74
  Bottom 0.178: v22.99,16.74 22.79,16.94 22.79,18.79 U1.24
PIO2_10  (via drill 0.3)
  Top 0.178: U2.2
  Top 0.305: v17.36,22.86 U2.2
  Bottom 0.178: U1.25 21.5,18.04 21.98,18.52 21.98,20.04 21.62,20.4 21.62,20.83 20.94,21.52 19.08,21.52 17.74,22.86 v17.36,22.86
PIO2_11  (via drill 0.3)
  Top 0.178: v14.38,25 14.26,25 13.19,26.06 R-MAT2.2.2
  Top 0.254: v15.81,21.62 14.94,21.62 v13.09,23.47
  Bottom 0.178: U1.31 18.5,18.08 16.7,19.89 16.7,21.11 16.19,21.62 v15.81,21.62 | v13.09,23.47 13.09,24.23 13.85,25 v14.38,25
PIO3
  Bottom 0.178: U1.14 23.87,23.79 24.14,24.06 24.14,28.55
  Bottom 1.016: R5.2 R2.2 24.14,28.55 R1.1
RSTN  (via drill 0.3)
  Top 0.178: 13.85,38.74 16.95,35.64 22.23,35.64 22.92,36.32 23.1,36.5 23.1,37.46 RESET.1
  Top 0.508: RESET.1 26.32,38.13 26.83,37.62 R15.1 | v13.67,28.68 13.95,28.4 v15.3,28.4 | 12.02,40.47 12.02,39.45 v12.43,39.04 12.73,38.74 13.85,38.74
  Top 1.016: 12.02,40.47 JTAG.5
  Bottom 0.178: U1.3 17,27.15 15.76,28.4 v15.3,28.4 | v13.67,28.68 13.42,28.93 13.42,29.49 10.75,32.16 10.75,35.21 12.56,37.01 12.56,38.92 v12.43,39.04
SWC  (via drill 0.3)
  Top 0.178: v10.12,35 10.24,35 11.11,35.87 11.11,37.21 R9.2
  Top 0.508: R9.2 10.32,39.4 9.52,40.2 9.52,40.48
  Top 1.016: 9.52,40.48 JTAG.3
  Bottom 0.165: 15.5,24.54 15.37,24.67
  Bottom 0.178: U1.29 19.5,17.87 19.49,17.88 19.49,18.98 19.08,19.38 18.22,19.38 17.41,20.2 17.41,21.41 15.88,22.94 15.88,23.19 15.53,23.55 15.53,24.51 15.5,24.54 | 15.37,24.67 15.22,24.82 15.22,26.04 14.64,26.62 14.64,27.16 14.18,27.61 13.85,27.61 13.04,28.43 13.04,29.36 10.4,32.01 10.4,34.72 v10.12,35
SWD  (via drill 0.3)
  Top 0.178: v8.9,32.18 8.57,32.51 8.57,34.34 10.32,36.1 R6.1
  Top 0.203: R6.1 9.43,37.37 9.43,39.32 8.27,40.49
  Top 0.508: v12.33,19.81 v12.33,21.74
  Top 1.016: 8.27,40.49 JTAG.2
  Bottom 0.178: v12.33,21.74 12.07,22 11.34,22 10.28,23.05 10.28,30.39 8.9,31.78 v8.9,32.18 | v12.33,19.81 12.35,19.79 U1.39
SWDCLK/TCLK
  Top 0.508: JTAG/SWD.9 5.9,23.75 8.21,26.06 R-MAT2.2.1
SWDIO/TMS  (via drill 0.4)
  Top 0.508: v7.96,26.95 R-MAT2.1.1 | JTAG/SWD.7 4.76,21.21 v7.96,24.41
  Bottom 0.508: v7.96,24.41 7.81,24.56 7.81,26.8 v7.96,26.95
SWO(V)/TDO  (via drill 0.4)
  Top 0.508: JTAG/SWD.13 v7.96,28.83 | v8.72,25.15 8.87,25.3 R-MAT2.3.1
  Bottom 0.508: v7.96,28.83 8.87,27.92 8.87,25.3 v8.72,25.15
SWO_EN  (via drill 0.3)
  Top 0.178: v15.81,19.41 17.33,19.41 18.04,20.12 v18.04,20.45 | U4.13 20.88,18.04 20.07,18.85 v20.07,19.2
  Bottom 0.178: U1.37 15.32,18.79 15.81,19.28 v15.81,19.41 | v18.04,20.45 18.75,19.74 19.54,19.74 v20.07,19.2
U2D+
  Bottom 0.178: R13.1 24.58,20.79 U1.20
  Bottom 1.016: C6.1 R13.1
U2D-
  Bottom 0.178: U1.19 23.86,21.29 24.14,21.57 24.14,21.87 R11.1
  Bottom 1.016: R11.1 C7.1
USB_SHIELD  (via drill 0.6)
  Top 0.254: 29.01,21.34 28.51,21.85 28.51,29.24 28,29.75
  Top 0.508: v29.01,19.94 29.01,21.34 | 28,29.75 v28,30.51
  Bottom 1.016: USB.P$6 28.34,31.88 28,31.54 v28,30.51 28.07,30.51 C5.1 | USB.P$5 29.38,18.16 29.01,18.53 v29.01,19.94
USB_VBUS  (via drill 0.4, 0.6)
  Top 0.508: VR1.3 31.11,31.59 30.79,31.9 30.16,31.9 | C9.1 29.21,28.89 VR1.1 29.21,31.9 | 30.16,31.9 29.21,31.9 | 29.21,31.9 27.29,31.9 v26.75,31.37 | v30.16,34.42 30.16,31.9 | v14.03,36.71 13.39,37.34 v11.87,37.34 | FUSE2.2 4.76,38.23 5.14,38.23 v7.3,36.07
  Top 1.016: USB.1 29.9,26.09 29.45,26.55 C9.1
  Bottom 0.508: R5.1 26.75,30.58 v26.75,31.37 | v30.16,34.42 29.01,35.56 16.8,35.56 15.65,36.71 v14.03,36.71 | v11.87,37.34 10.98,36.45 7.68,36.45 v7.3,36.07
VCC  (via drill 0.3, 0.4, 0.6)
  Top 0.203: C11.1 23.63,16.16 23.63,17.02 22.74,17.91 22.74,18.37 22.42,18.69 U4.14 | 4.13,9.94 FUSE1.1
  Top 0.254: U2.14 16.7,27.84 15.7,27.84 15.6,27.74 12.83,27.74 v12.4,28.17 | v22.94,27.31 23.66,27.31
  Top 0.356: 21.65,33.86 U3.14
  Top 0.457: 21.65,35.13 21.65,33.86 | 21.65,35.13 23.53,35.13 | v15.45,35.71 16.04,35.13 21.65,35.13
  Top 0.508: T2.2 31.54,12.79 30.28,11.53 28.79,11.53 v28.48,11.23 28.15,11.23 27.54,10.62 R3.1 | 10.42,15.32 R18.2 | v29.19,36.71 C8.1 29.01,35.49 29.01,34.04 29.21,33.85 VR1.5 | R15.2 24.95,35.51 v24.95,36.58 | R15.2 25.05,35.15 23.53,35.15 | v10.32,15.32 10.42,15.32 | 10.42,15.32 10.42,20.91 v10.14,21.19 | R8.2 23.58,25.35 23.58,24.67 23.25,24.34 23.25,20.45 25.51,18.19 v25.51,15.88 C11.1 | v12.4,28.17 12.07,28.17 11.54,28.7 C10.1 | R15.2 24.85,35.21 24.85,32.36 | 23.66,27.31 C12.1 | v22.94,27.31 23.99,27.31 23.99,31.75 24.59,32.36 24.85,32.36 | 23.53,35.15 R7.2 | 23.53,35.15 23.53,35.13 23.53,35.11 | v9.61,34.09 13.34,34.09 14.03,34.78 v14.03,35.71 | 24.85,32.36 v25.15,32.36 | FUSE1.1 6.92,12.83 6.92,14.86 7.65,15.6 v7.78,15.6 | 1.46,41.79 2.85,40.39 6.46,40.39
  Top 0.61: 7.78,16.56 R14.2 | 8.49,36.48 8.24,36.48 6.46,38.25 6.46,38.56 | v8.49,35.44 8.49,36.48 | 8.49,36.48 R6.2
  Top 0.762: v7.78,15.6 7.78,16.56
  Top 1.016: 6.46,38.56 6.46,40.39 6.46,40.97 JTAG.1 | C12.1 R8.2 | 4.13,9.94 3.79,9.6 3.79,8.82 1.46,6.48 LED3.1-A
  Top 1.778: LED3.1-A PWR.1-A | LED1.1-A LED2.1-A 1.46,41.79
  Bottom 0.254: U1.44 13.58,22.29 13.24,21.95 13.24,21.69 12.63,21.08 11.29,21.08 C4.1 | U1.8 19.5,26.71 20.96,28.17 21.93,28.17 21.93,28.32 | v25.15,32.36 25.59,31.93 25.59,30.94 R2.1
  Bottom 0.305: v12.4,28.17 12.4,29.39 9.96,31.83 9.96,33.73 v9.61,34.09
  Bottom 0.508: v24.95,36.58 25.2,36.32 28.81,36.32 v29.19,36.71 | v28.48,11.23 27.72,11.23 25.92,13.03 25.92,15.47 v25.51,15.88 | v22.94,27.31 21.93,28.32 C1.1 | v14.03,35.71 v15.45,35.71
  Bottom 0.61: v7.78,15.6 8.06,15.32 v10.32,15.32 | C4.1 v10.14,21.19 9.71,21.62 9.71,30.13 8.06,31.78 8.06,34.09 | 8.06,34.09 8.06,35 v8.49,35.44 | 8.06,34.09 v9.61,34.09

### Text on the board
Top: Za seriqta v Kitaj -> 1.5mm debelina na platkata!
tNames: A | A | A | A
bNames: C | C | Rev.C (C)2012 | RoHS Compliant | ARM-JTAG-COOCOX | WWW.OLIMEX.COM/DEV | C | C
